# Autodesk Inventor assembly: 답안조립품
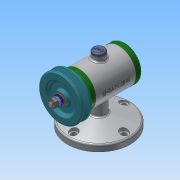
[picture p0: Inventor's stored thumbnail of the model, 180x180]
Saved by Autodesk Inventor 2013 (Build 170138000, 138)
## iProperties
Created: 2018-12
Part Number: 답안조립품
Document SubType Name: Assembly
Designer: Administrator
Author: Administrator
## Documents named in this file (15)
- C:\Users\Administrator\Desktop\481207V1067\답안조립품.iam
- C:\Users\Administrator\Desktop\481207V1067\본체.ipt
- C:\Users\Administrator\Desktop\481207V1067\뒤커버.ipt
- C:\Users\Administrator\Desktop\481207V1067\앞커버.ipt
- C:\Users\Administrator\Desktop\481207V1067\베어링 15 x 32 x 9.ipt
- C:\Users\Administrator\Desktop\481207V1067\오일 실 15 25 7.ipt
- C:\Users\Administrator\Desktop\481207V1067\고무캡.ipt
- C:\Users\Administrator\Desktop\481207V1067\축.ipt
- C:\Users\Administrator\Desktop\481207V1067\V벨트풀리.ipt
- C:\Users\Administrator\Desktop\481207V1067\스프링와셔 8.ipt
- C:\Users\Administrator\Desktop\481207V1067\와셔 8x17.ipt
- C:\Users\Administrator\Desktop\481207V1067\키 3 x 3 x 12.ipt
- C:\Users\Administrator\Desktop\481207V1067\볼트 M4 x 12.ipt
- C:\Users\Administrator\Desktop\481207V1067\너트 M8.ipt
- 너트 M8.ipt
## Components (2 placed, 2 different names)
1. 고무캡:1
2. V벨트풀리:1 — 각도:2
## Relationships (1: Angle 1)
- 각도:2 [Angle]: V벨트풀리:1
